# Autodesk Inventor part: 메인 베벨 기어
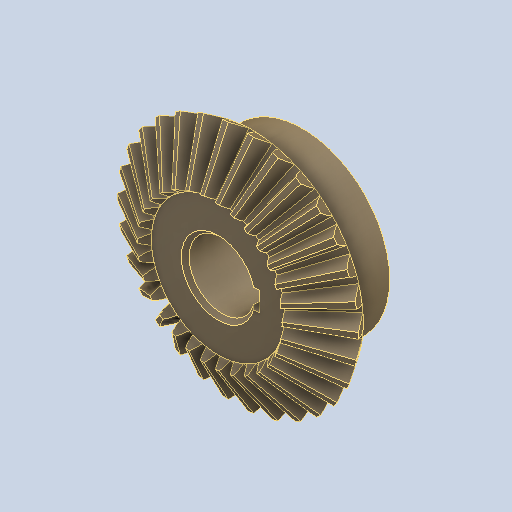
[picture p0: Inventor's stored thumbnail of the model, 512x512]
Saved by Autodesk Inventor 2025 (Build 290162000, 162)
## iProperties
Created: 2024-07
Part Number: 메인 베벨 기어
Material: 강철, 탄소
Document SubType Name: Modeling
Designer: hsj03
Density: 7.87 g/cm^3
Appearance: 기본값
Author: jhkim
Revision Number: 1
Sending System: Autodesk Inventor 2025
Preprocessor: ST-DEVELOPER v20
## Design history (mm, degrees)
feature "Solid1"
node "솔리드1"
